Omron CX-Programmer project NuevoProyecto (CX-Programmer 9.50)

# PLC NewPLC1: CP1L-E EM

## Program P11 (cyclic task 0)
Local symbols
Etapa_0 10.00 BOOL
Etapa_1 10.01 BOOL
Etapa_2 10.02 BOOL
Etapa_3 10.03 BOOL
Etapa_4 10.04 BOOL
Etapa_5 10.05 BOOL
Etapa_6 10.06 BOOL
Etapa_7 10.07 BOOL
Etapa_8 10.08 BOOL
F1 0.01 BOOL
F2 0.02 BOOL
F3 0.03 BOOL
F4 0.04 BOOL
FSP 15.00 BOOL  ; Flanco Subida de P
P 0.00 BOOL
Pm 15.01 BOOL  ; Pulsador memorizado
Rd1 100.00 BOOL
Rd2 100.02 BOOL
Ri1 100.01 BOOL
Ri2 100.03 BOOL

### Section Sección1_Programa_principal
; Etapas 0 ... 8

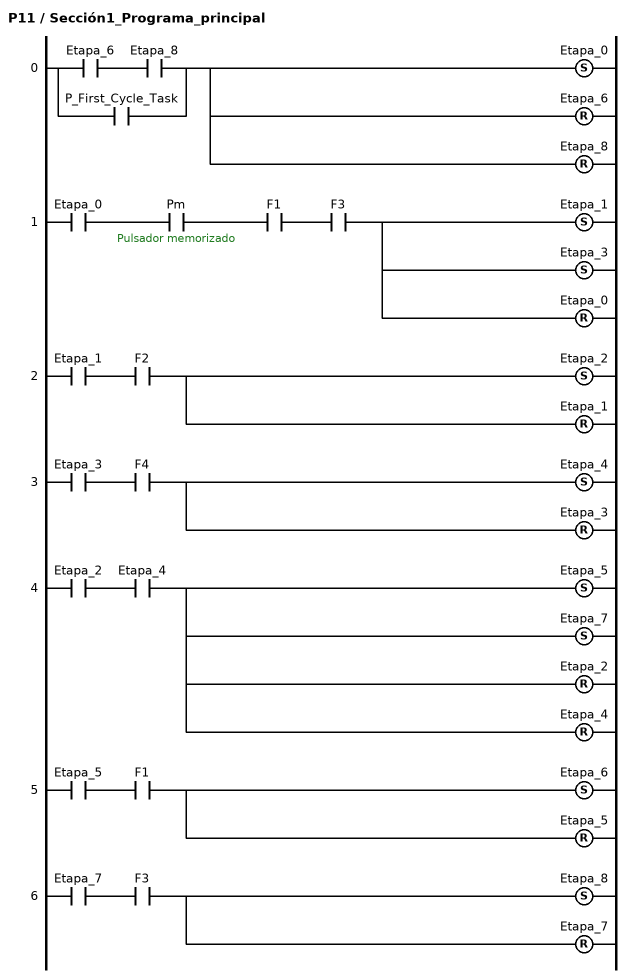
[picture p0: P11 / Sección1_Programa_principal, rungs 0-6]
; rung 0
LD Etapa_6
AND Etapa_8
OR P_First_Cycle_Task
SET Etapa_0
RSET Etapa_6
RSET Etapa_8
; rung 1
LD Etapa_0
AND Pm  ; Pulsador memorizado
AND F1
AND F3
SET Etapa_1
SET Etapa_3
RSET Etapa_0
; rung 2
LD Etapa_1
AND F2
SET Etapa_2
RSET Etapa_1
; rung 3
LD Etapa_3
AND F4
SET Etapa_4
RSET Etapa_3
; rung 4
LD Etapa_2
AND Etapa_4
SET Etapa_5
SET Etapa_7
RSET Etapa_2
RSET Etapa_4
; rung 5
LD Etapa_5
AND F1
SET Etapa_6
RSET Etapa_5
; rung 6
LD Etapa_7
AND F3
SET Etapa_8
RSET Etapa_7

### Section Sección2_Paro_memorizado

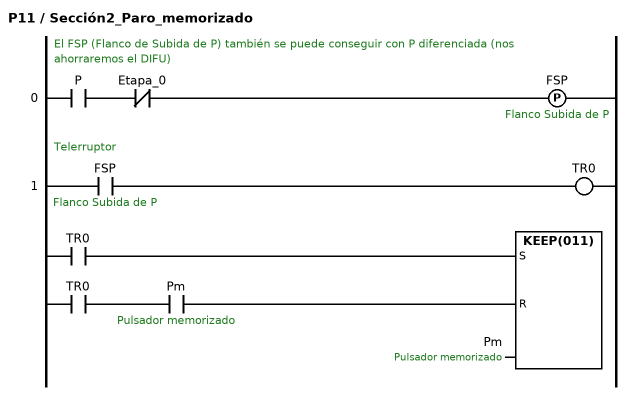
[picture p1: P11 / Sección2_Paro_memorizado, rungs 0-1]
; rung 0: El FSP (Flanco de Subida de P) también se puede conseguir con P diferenciada (nos ahorraremos el DIFU)
LD P
ANDNOT Etapa_0
DIFU(013) FSP  ; Flanco Subida de P
; rung 1: Telerruptor
LD FSP  ; Flanco Subida de P
OUT TR0
LD TR0
AND Pm  ; Pulsador memorizado
KEEP(011) Pm  ; Pulsador memorizado

### Section Sección3_Salidas
; Salidas

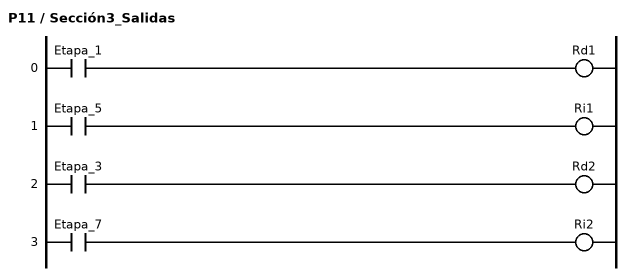
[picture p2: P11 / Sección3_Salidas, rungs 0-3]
; rung 0
LD Etapa_1
OUT Rd1
; rung 1
LD Etapa_5
OUT Ri1
; rung 2
LD Etapa_3
OUT Rd2
; rung 3
LD Etapa_7
OUT Ri2

### Section Sección4_END
; rung 0
END(001)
